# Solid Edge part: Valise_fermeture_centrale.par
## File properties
Author: Bernard DUMAS
Template: Normal.par
Last saved by: FR026244
Revision: 27
Application: Solid Edge
Densité: 7750.000 kg/m^3
Précision: 0.9900
Document Number: 13
Revision: a
Project Name: Slamson
Material: Acier inoxydable
Style de face: Argent
Style de remplissage: ANSI32(Acier)
Style virtuel: Acier inoxydable
Coef. of Thermal Exp: 0.0
Thermal Conductivity: 17.0
Specific Heat: 502.0
Modulus of Elasticity: 193053196000.0
Poission's Ratio: 0.29
Yield Stress: 310264065.0
Ultimate Stress: 641212401.0
Elongation: 0.0
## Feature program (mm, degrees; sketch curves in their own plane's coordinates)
sketch used by "unnamed Protrusion 1" plane through (0, 0, 0) normal (0, -1, 0) x-axis (1, 0, 0)
extrude "unnamed Protrusion 1" add finite 1 along +normal
mirror "unnamed Mirror 1" of "unnamed Protrusion 1" about plane through (0, 0, 0) normal (1, 0, 0)
extrude "unnamed Protrusion 2" add finite 1
sketch for "Perçage_7" plane through (0, -1, -10) normal (0, -1, 0) x-axis (1, 0, 0)
  hole centre (-14, 22) bore radius 1.5
hole "Perçage_7" diameter 3 through
sketch for "unnamed Hole 1" plane through (0, -1, -10) normal (0, -1, 0) x-axis (1, 0, 0)
  hole centre (0, 34) bore radius 1.5
hole "unnamed Hole 1" through
sketch for "unnamed Hole 2" plane through (0, -1, -10) normal (0, -1, 0) x-axis (1, 0, 0)
  hole centre (14, 22) bore radius 1.5
hole "unnamed Hole 2" through
sketch for "unnamed Hole 3" plane through (0, -1, -10) normal (0, -1, 0) x-axis (1, 0, 0)
  hole centre (-18, 4) bore radius 1.5
hole "unnamed Hole 3" through
sketch for "unnamed Hole 4" plane through (0, -1, -10) normal (0, -1, 0) x-axis (1, 0, 0)
  hole centre (18, 4) bore radius 1.5
hole "unnamed Hole 4" through
sketch for "unnamed Hole 5" plane through (0, -1, -10) normal (0, -1, 0) x-axis (1, 0, 0)
  hole centre (0, -34) bore radius 1.5
hole "unnamed Hole 5" through
pattern "unnamed Pattern 1" of "Perçage_7", "unnamed Hole 1", "unnamed Hole 2", "unnamed Hole 3", "unnamed Hole 4", "unnamed Hole 5"
sketch for "unnamed Cutout 1" plane through (0, -1, -10) normal (0, -1, 0) x-axis (1, 0, 0)
  line (-24, 10) -> (24, 10)
  line (24, 10) -> (24, 10.5)
  line (24, 10.5) -> (-24, 10.5)
  line (-24, 10.5) -> (-24, 10)
  dimension (linear) = 24
extrude "unnamed Cutout 1" cut through along -normal
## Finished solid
Body 1: solid body, 26 faces, 60 edges, 32 vertices, 2 separate solids.
  Faces by surface: cylinder 20, plane 6
  Edges by curve: circle 40, line 20
Bounding box of the edges (mm): 48.000 x 1.000 x 80.000, from (-24, -1, -50) to (24, 0, 30).
Cylindrical faces by radius (mm): R1.5 x6, R6 x10, R9.9134 x2, R36 x2
Planar faces by outward normal: +y 2, +z 1, -y 2, -z 1
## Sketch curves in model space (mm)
line (24, 0, -50) -> (24, 0, 30)
line (24, 0, 30) -> (-24, 0, 30)
line (-24, 0, 30) -> (-24, 0, -50)
line (-24, 0, -50) -> (24, 0, -50)
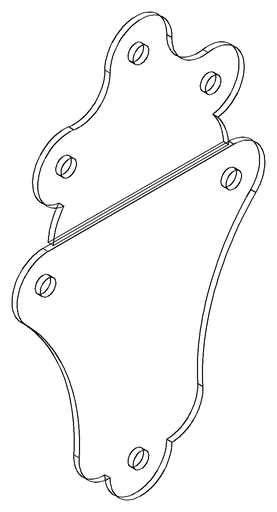
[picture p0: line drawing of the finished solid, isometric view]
